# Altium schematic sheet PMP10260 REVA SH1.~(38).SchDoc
size 431 x 279 mm; Date: Not shown in title block; ApprovedBy: Not shown in title block; CheckedBy: Not shown in title block; Author: Not shown in title block; CompanyName: Not shown in title block; Engineer: Not shown in title block; Organization: Not shown in title block; Address1: Not shown in title block; Address2: Not shown in title block; Address3: Not shown in title block; Address4: Not shown in title block; DocumentNumber: 1; Revision: Use project parameter SCH_Rev; SheetNumber: 1; SheetTotal: 4; PageSetup: Record=PageOptions|CenterHorizontal=True|CenterVertical=True|PrintScale=1.00|XCorrection=1.00|YCorrection=1.00|PrintKind=0|BorderSize=5000000|LeftOffset=0|BottomOffset=0|Orientation=2|PaperLength=1000|PaperWidth=1000|Scale=100|PaperSource=15|PrintQuality=600|MediaType=1|DitherType=10|PaperKind=Letter|PrintScaleMode=1
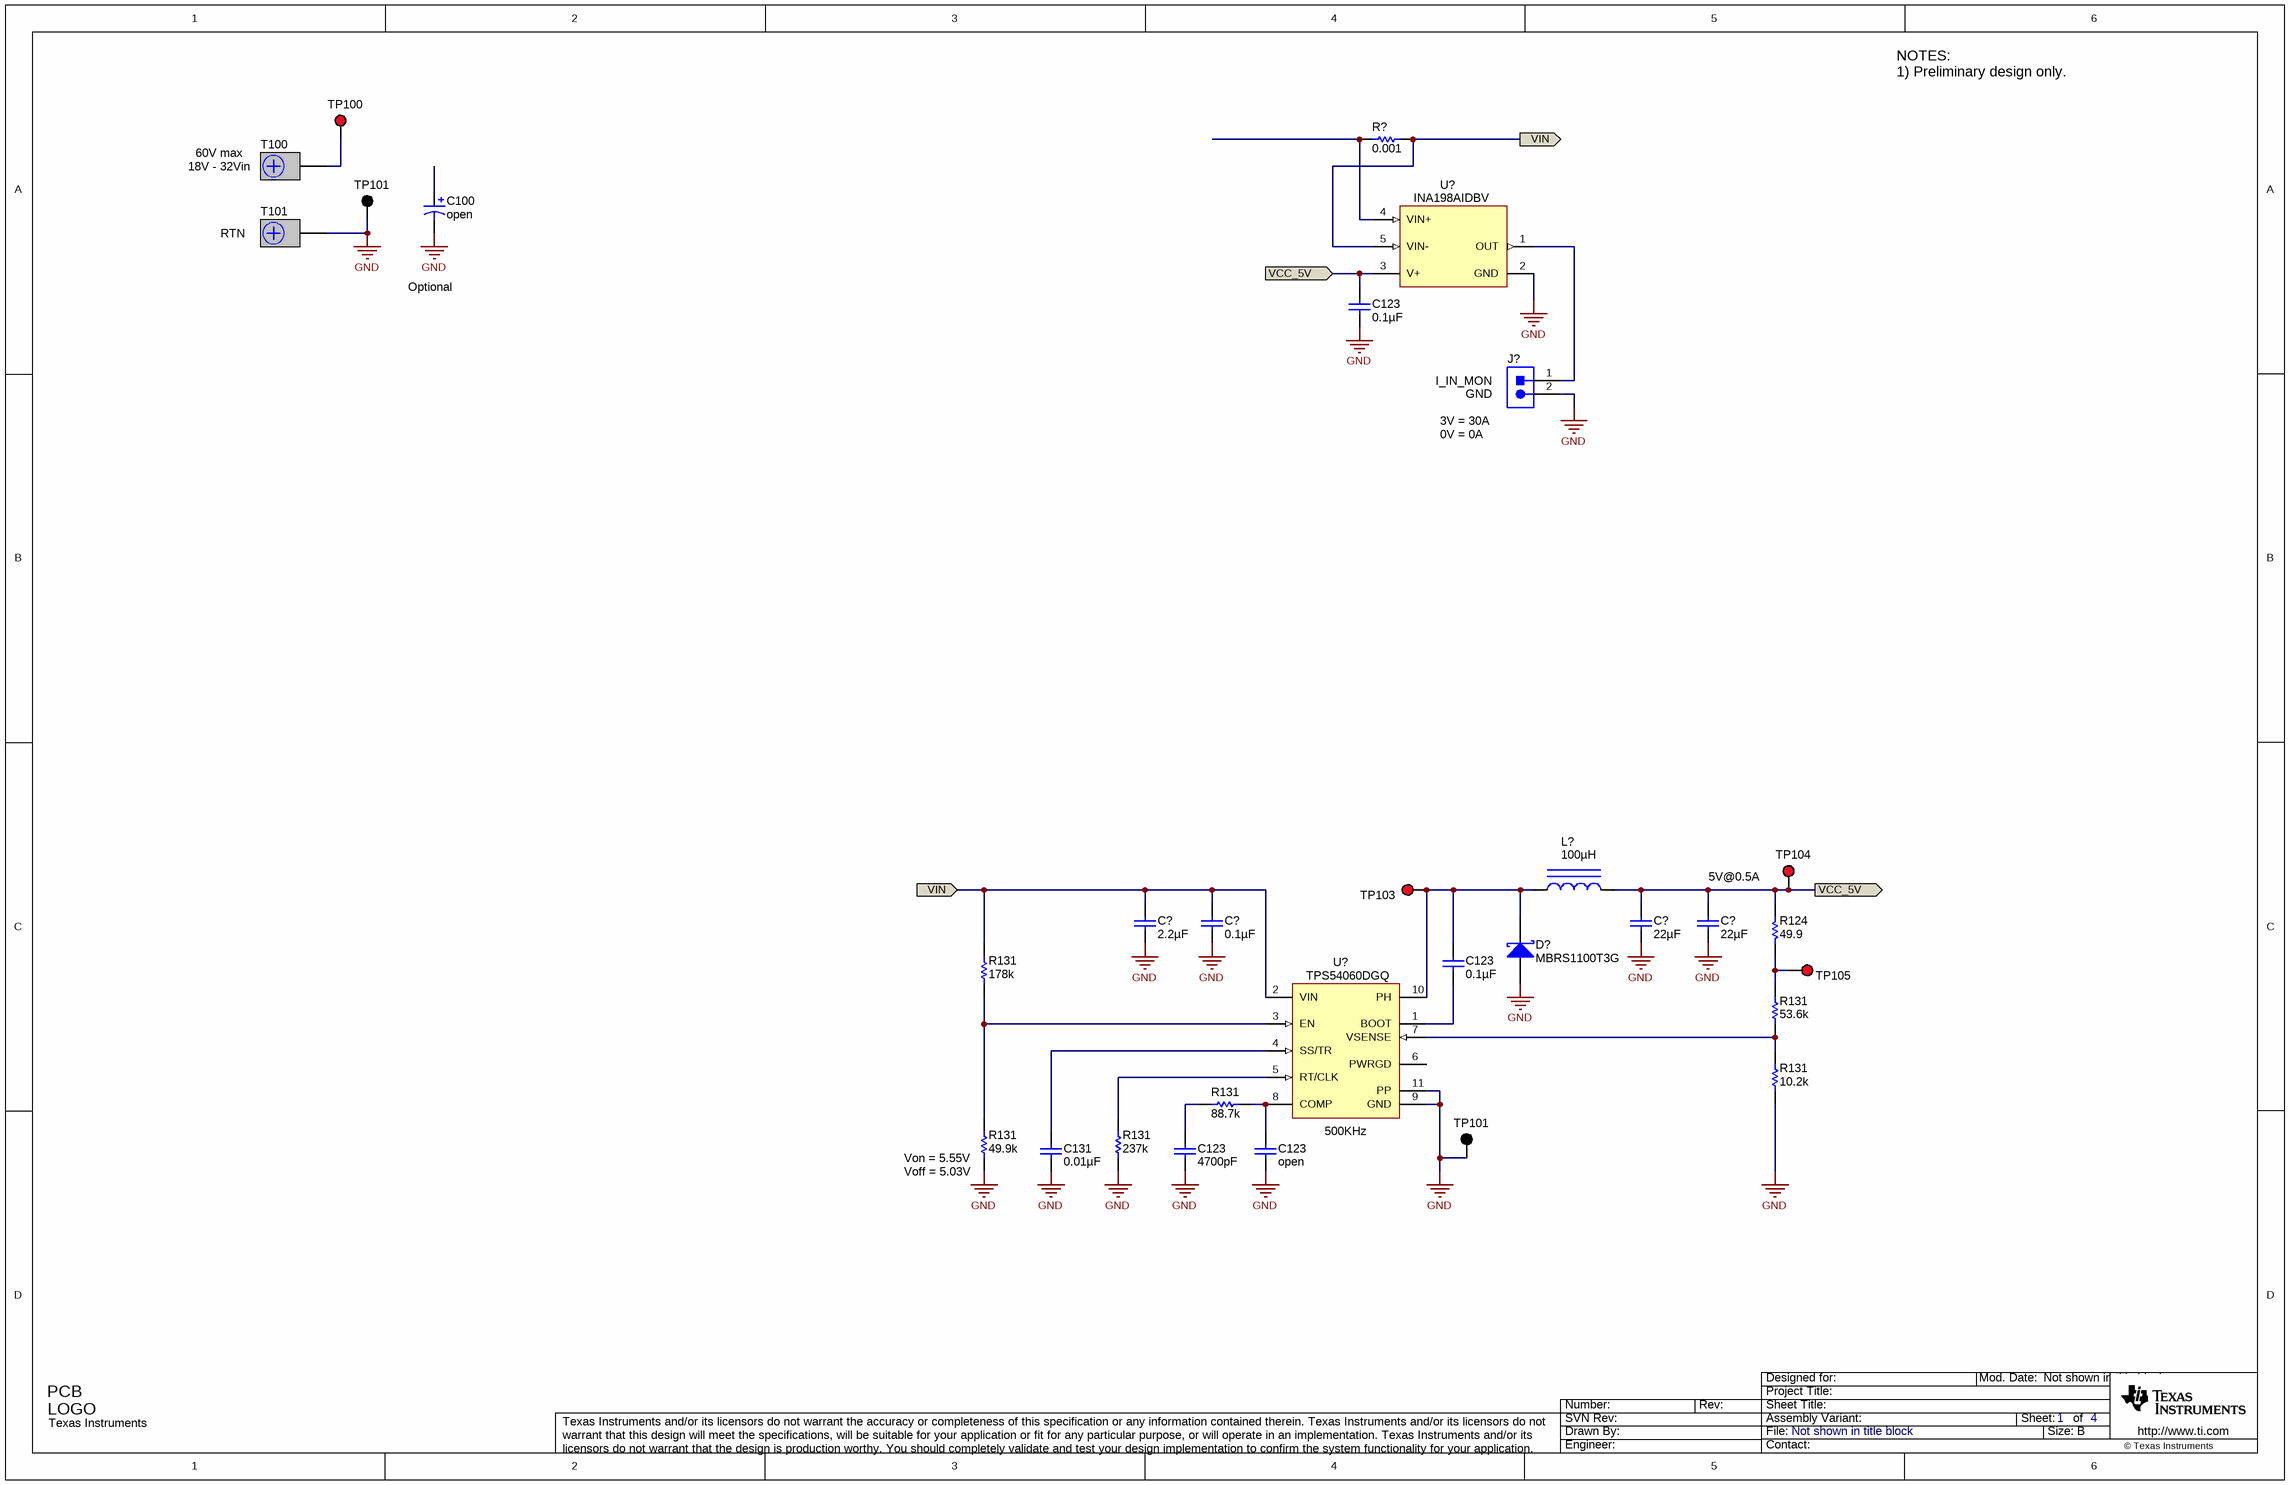
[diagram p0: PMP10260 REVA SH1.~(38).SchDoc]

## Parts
(Parts that share a designator on the sheet are numbered #1, #2 ... from top to bottom, then left to right.)
C100  ValueDisplayed: open  [SM_RADIAL_8MM]
C123#1  ValueDisplayed: 0.1µF  [0603L]  (hidden comment: C1608X7R1H104K)
C123#2  ValueDisplayed: 0.1µF  [0603L]  (hidden comment: C1608X7R1H104K)
C123#3  ValueDisplayed: 4700pF  [0603]  (hidden comment: C1608C0G1H472J)
C123#4  ValueDisplayed: open  [0603L]
C131  ValueDisplayed: 0.01µF  [0603]  (hidden comment: C1608X7R1H103K)
C?#1  ValueDisplayed: 2.2µF  [1210]  (hidden comment: GRM32ER72A225KA35L)
C?#2  ValueDisplayed: 0.1µF  [0603]  (hidden comment: GRM188R72A104KA35D)
C?#3  ValueDisplayed: 22µF  [1210]  (hidden comment: C3225X7R1C226M)
C?#4  ValueDisplayed: 22µF  [1210]  (hidden comment: C3225X7R1C226M)
D?  MBRS1100T3G  [SMB]
J?  PEC02SAAN  [CONN_PEC02SAAN]  (value not drawn)
L?  ValueDisplayed: 100µH  [MSS1048]  (hidden comment: MSS1048-104MLB)
Logo100  Texas Instruments  [TI_Stacked_Overlay_Small]  (no BOM)
R124  value 49.9  [0603]  (hidden comment: CRCW060349R9FKEA)
R131#1  value 178k  [0603]  (hidden comment: CRCW0603178KFKEA)
R131#2  value 53.6k  [0603]  (hidden comment: CRCW060353K6FKEA)
R131#3  value 10.2k  [0603]  (hidden comment: CRCW060310K2FKEA)
R131#4  value 88.7k  [0603]  (hidden comment: CRCW060388K7FKEA)
R131#5  value 49.9k  [0603]  (hidden comment: CRCW060349K9FKEA)
R131#6  value 237k  [0603]  (hidden comment: CRCW0603237KFKEA)
R?  value 0.001  [CSS2725_0005]  (hidden comment: CSS2725FT1L00)
T100  CB35-36-CY  [CB35-36-CY]  (value not drawn)
T101  CB35-36-CY  [CB35-36-CY]  (value not drawn)
TP100  5010  [Keystone5010]  (value not drawn)
TP101#1  5011  [Keystone5011]  (value not drawn)
TP101#2  5011  [Keystone5011]  (value not drawn)
TP103  5010  [Keystone5010]  (value not drawn)
TP104  5010  [Keystone5010]  (value not drawn)
TP105  5010  [Keystone5010]  (value not drawn)
U?#1  INA198AIDBV  [DBV0005A_N]
U?#2  TPS54060DGQ  [DGQ0010D_N]

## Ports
VCC_5V, VIN

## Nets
GND: C100.2(-) C123#1.2 C123#3.2 C123#4.2 C131.2 C?#1.2 C?#2.2 C?#3.2 C?#4.2 D?.2(A) J?.2 R131#3.1 R131#5.1 R131#6.1 T101.1 TP101#1.1 TP101#2.1 U?#1.2(GND) U?#2.9(GND) U?#2.11(PP)
VCC_5V: C123#1.1 C?#3.1 C?#4.1 L?.2 R124.2 TP104.1 U?#1.3(V+) ; port VCC_5V
VIN: C?#1.1 C?#2.1 R131#1.2 R?.2 U?#1.5(VIN-) U?#2.2(VIN) ; port VIN
NetC123#2_1: C123#2.1 D?.1(K) L?.1 TP103.1 U?#2.10(PH)
NetC123#2_2: C123#2.2 U?#2.1(BOOT)
NetC123#3_1: C123#3.1 R131#4.2
NetC123#4_1: C123#4.1 R131#4.1 U?#2.8(COMP)
NetC131_1: C131.1 U?#2.4(SS/TR)
NetJ?_1: J?.1 U?#1.1(OUT)
NetR124_1: R124.1 R131#2.2 TP105.1
NetR131#1_1: R131#1.1 R131#5.2 U?#2.3(EN)
NetR131#2_1: R131#2.1 R131#3.2 U?#2.7(VSENSE)
NetR131#6_2: R131#6.2 U?#2.5(RT/CLK)
NetR?_1: R?.1 U?#1.4(VIN+)
NetT100_1: T100.1 TP100.1

Not connected (* = marked no-connect by the designer): C100 1(+); U?#2 6(PWRGD)

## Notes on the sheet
- (near T100) 18V - 32Vin
- 60V max
- NOTES:
  1) Preliminary design only.
- RTN
- Optional
- (near J?) 3V = 30A
- 0V = 0A
- (near J?) I_IN_MON
- (near J?) GND
- 5V@0.5A
- (near R131#5) Von = 5.55V
- (near R131#5) Voff = 5.03V
- (near U?#2) 500KHz

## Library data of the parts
C100 = 20SVP100M: CAP, OS-CON, open; Manufacturer: Sanyo; Polarized: Y; CompType: Capacitor; Value: 82uF; U/M: EA; Cap_F: 0.0001; Tolerance_%: 20; Value1: 0.020 ohm; VDC_V: 35; Value2: 35V; ESR_Ohm: 0.024; IRMS_A: 3.32; TaMin_C: -55; TaMax_C: 105; Cap_Case: 8.3x8.3x11.9
C123#1 C123#2 = C1608X7R1H104K: CAP, CERM, 0.1uF, 50V, +/-10%, X7R, 0603; Manufacturer: TDK; Polarized: N; CompType: Capacitor; U/M: EA; Cap_F: 0.0000001; Tolerance_%: 10; ESR_Ohm: 0.017; Value1: 0.017 ohm; VDC_V: 50; TaMin_C: -55; TaMax_C: 125; Cap_Case: 0603
C123#3 = C1608C0G1H332J: CAP, CERM, 4700pF, 50V, +/-5%, C0G/NP0, 0603; Manufacturer: TDK; Polarized: N; CompType: Capacitor; Value: 3300pF; U/M: EA; Cap_F: 0.0000000033; Tolerance_%: 5; ESR_Ohm: 0.0309; Value1: 0.0309 ohm; VDC_V: 50; TaMin_C: -55; TaMax_C: 125
C123#4 = C1608X7R1H104K: CAP, open, 0603; Polarized: N; CompType: Capacitor; U/M: EA; Cap_F: 0.0000001; Tolerance_%: 10; ESR_Ohm: 0.017; TempCo: X7R; TaMin_C: -55; TaMax_C: 125; Cap_Case: 0603
C131 = C1608X7R1H103K: CAP, CERM, 0.01uF, 50V, +/-10%, X7R, 0603; Manufacturer: TDK; Polarized: N; CompType: Capacitor; U/M: EA; Cap_F: 0.00000001; Tolerance_%: 10; ESR_Ohm: 0.0539; Value1: 0.0539 ohm; VDC_V: 50; TaMin_C: -55; TaMax_C: 125
C?#1 = GRM32ER72A225KA35L: CAP, CERM, 2.2uF, 100V, +/-10%, X7R, 1210; Manufacturer: MuRata; Polarized: N; CompType: Capacitor; U/M: EA; Cap_F: 0.0000022; Tolerance_%: 10; ESR_Ohm: 0.007; Value1: 0.007 ohm; VDC_V: 100; IRMS_A: 4.4; TaMin_C: -55; TaMax_C: 125
C?#2 = GRM188R72A104KA35D: CAP, CERM, 0.1uF, 100V, +/-10%, X7R, 0603; Manufacturer: MuRata; Polarized: N; CompType: Capacitor; U/M: EA; Cap_F: 0.0000001; Tolerance_%: 10; Value1: Unknown; VDC_V: 100; TaMin_C: -55; TaMax_C: 125
C?#3 C?#4 = C3225X7R1C226M: CAP, CERM, 22uF, 16V, +/-20%, X7R, 1210; Manufacturer: TDK; Polarized: N; CompType: Capacitor; U/M: EA; Cap_F: 0.000022; Tolerance_%: 20; ESR_Ohm: 0.002; Value1: 0.002 ohm; VDC_V: 16; IRMS_A: 8.11; TaMin_C: -55; TaMax_C: 125
D? = MBRS1100T3G: Diode, Schottky, 100V, 1A, SMB; Manufacturer: ON Semiconductor; U/M: EA; Vf_V: 0.75; Value2: 0.75V; Io_A: 1; Vr_V: 100; TJmax_C: 150; RJC_CperW: 22
J? = PEC02SAAN: Header, 100mil, 2x1, Tin, TH; Manufacturer: Sullins Connector Solutions; SymbolCreator: a0412235; U/M: EA
L? = MSS1048-104MLB: Inductor, Shielded Drum Core, Ferrite, 100uH, 1.36A, 0.25 ohm, SMD; Manufacturer: Coilcraft; Ind_H: 100.0E-6; Imax_A: 1.36; Irms: 1.48A @ 40C rise; Isat: 1.36A @ 30% inductance drop; DCR_ohm: 0.25
Logo100 = TI_Logo: Texas Instrument Corporate Signature; SymbolCreator: codlsc
R124 = CRCW060349R9FKEA: RES, 49.9 ohm, 1%, 0.1W, 0603; Manufacturer: Vishay-Dale; CompType: Resistor; Value_Code: 49R9; Tolerance_%: 1; Power_W: 0.1; VDC_V: 75; TempCo: 100 ppm/C; EIA_Code: E96; U/M: EA
R131#1 = CRCW0603178KFKEA: RES, 178k ohm, 1%, 0.1W, 0603; Manufacturer: Vishay-Dale; CompType: Resistor; Res_ohm: 178000; Tolerance_%: 1; Power_W: 0.1; VDC_V: 75; TempCo: 100 ppm/C; EIA_Code: E96; U/M: EA
R131#2 = CRCW060353K6FKEA: RES, 53.6k ohm, 1%, 0.1W, 0603; Manufacturer: Vishay-Dale; CompType: Resistor; Res_ohm: 53600; Value_Code: 53k6; Tolerance_%: 1; Power_W: 0.1; VDC_V: 75; TempCo: 100 ppm/C; EIA_Code: E96; U/M: EA
R131#3 = CRCW060310K2FKEA: RES, 10.2k ohm, 1%, 0.1W, 0603; Manufacturer: Vishay-Dale; CompType: Resistor; Res_ohm: 10200; Value_Code: 10k2; Tolerance_%: 1; Power_W: 0.1; VDC_V: 75; TempCo: 100 ppm/C; EIA_Code: E96; U/M: EA
R131#4 = CRCW060388K7FKEA: RES, 88.7k ohm, 1%, 0.1W, 0603; Manufacturer: Vishay-Dale; CompType: Resistor; Res_ohm: 88700; Value_Code: 88k7; Tolerance_%: 1; Power_W: 0.1; VDC_V: 75; TempCo: 100 ppm/C; EIA_Code: E96; U/M: EA
R131#5 = CRCW060349K9FKEA: RES, 49.9k ohm, 1%, 0.1W, 0603; Manufacturer: Vishay-Dale; CompType: Resistor; Res_ohm: 49900; Value_Code: 49k9; Tolerance_%: 1; Power_W: 0.1; VDC_V: 75; TempCo: 100 ppm/C; EIA_Code: E96; U/M: EA
R131#6 = CRCW0603237KFKEA: RES, 237k ohm, 1%, 0.1W, 0603; Manufacturer: Vishay-Dale; CompType: Resistor; Res_ohm: 237000; Tolerance_%: 1; Power_W: 0.1; VDC_V: 75; TempCo: 100 ppm/C; EIA_Code: E96; U/M: EA
R? = CSS2725FTL500: RES, 0.001 ohm, 1%, 4W, RES_2725; Manufacturer: Stackpole Electronics Inc; CompType: Resistor; Res_ohm: 0.0005; Value_Code: R001; Tolerance_%: 1; Power_W: 4; TempCo: 50 ppm/C; U/M: EA
T100 T101 = CB35-36-CY: Terminal 50A Lug; Manufacturer: Panduit; SymbolCreator: crossc; CompType: Screw Terminal; U/M: EA
TP100 TP103-TP105 = 5010: Test Point, Multipurpose, Red, TH; Manufacturer: Keystone; CompType: Test Point Loop; U/M: EA
TP101#1 TP101#2 = 5011: Test Point, Multipurpose, Black, TH; Manufacturer: Keystone; CompType: Test Point Loop; U/M: EA
U?#1 = INA198AIDBV: CURRENT SHUNT MONITOR -16V to +80V Common-Mode Range, DBV0005A; Alternate Manufacturer: None; Manufacturer: Texas Instruments; SymbolCreator: a0411947; CompType: IC; U/M: EA
U?#2 = TPS54060DGQ: Buck Inverting Buck-Boost Step Down Regulator with 3.5 to 60 V Input and 0.8 to 58 V Output, -40 to 150 degC, 10-Pin MSOP-PowerPAD (DGQ), Green (RoHS & no Sb/Br); Manufacturer: Texas Instruments; Alternate Manufacturer: None; Alternate PartNumber: Equivalent; Duty Cycle(Max)(%): 98; Iout(Max)(A): 0.5; Iq(Typ)(mA): 0.116; Rating: Catalog; Regulated Outputs(#): 1; SubFamily: Step-Down Regulator; Switch Current Limit(Typ)(A): 0.6; Topology: Buck, Inverting Buck-Boost; Vin(Max)(V): 60; Vin(Min)(V): 3.5; Vout(Max)(V): 58; Vout(Min)(V): 0.8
